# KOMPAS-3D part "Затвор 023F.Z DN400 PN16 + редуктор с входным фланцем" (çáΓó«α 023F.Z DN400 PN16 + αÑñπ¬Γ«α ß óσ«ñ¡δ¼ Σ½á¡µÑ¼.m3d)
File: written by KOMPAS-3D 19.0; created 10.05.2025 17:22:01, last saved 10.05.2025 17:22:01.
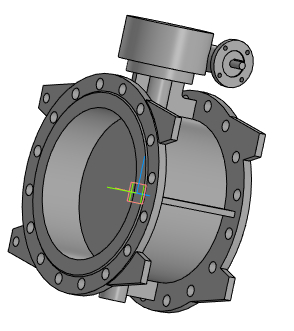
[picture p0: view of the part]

Document properties: Полное имя файла: Затвор 023F.Z DN400 PN16 + редуктор с входным фланцем.a3d

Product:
- Part/product: Затвор 023F.Z DN400 PN16 + редуктор с входным фланцем
    Масса: 199.363

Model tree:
1. Операция без истории:1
